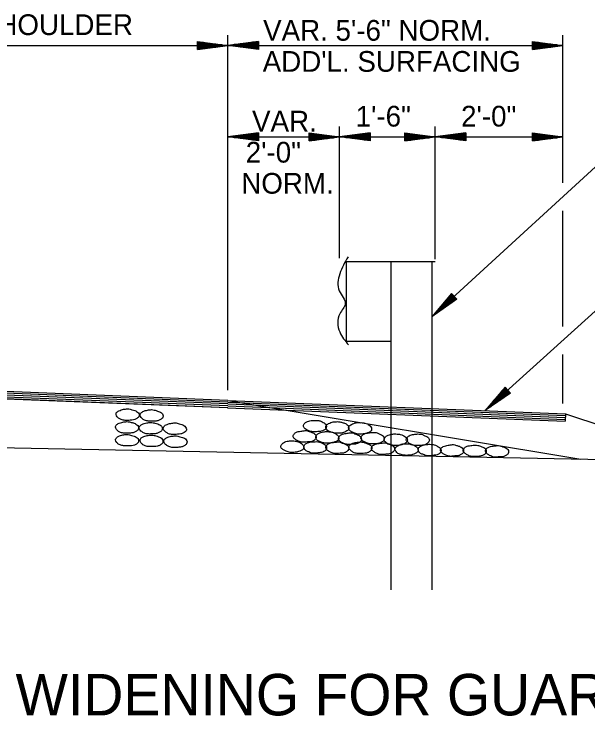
# Model space of a CAD drawing. Extents: x -2842 to 2681, y -2139 to 474.
# Drawn here: x 439.5 to 605.6, y -1543.1 to -1339.9 of the extents above; entities that cross this region are included whole.
import ezdxf

# ---------------------------------------------------------------- set-up
doc = ezdxf.new("R2010")
doc.units = 0
for name, color, linetype in [('BDR_Plan Profile Grid 3', 7, 'Continuous'), ('R_Border', 7, 'Continuous'), ('R_Border Notes', 7, 'Continuous'), ('SHT_NPLT', 7, 'Continuous')]:
    doc.layers.add(name, color=color, linetype=linetype)

msp = doc.modelspace()

# ---------------------------------------------------------------- linework, layer by layer
at = {"layer": 'BDR_Plan Profile Grid 3'}
for p, q in [((501.39, -1451.78), (394.39, -1447.45)), ((501.39, -1452.27), (394.39, -1448.03)), ((501.39, -1452.8), (394.39, -1448.57)), ((501.35, -1453.92), (394.35, -1449.59)), ((501.39, -1453.38), (394.39, -1449.1)), ((501.35, -1453.96), (394.39, -1449.68)), ((501.39, -1451.78), (603.52, -1468.78)), ((356.1, -1463.82), (640.63, -1469.52))]:
    msp.add_line(p, q, dxfattribs=at)
for points in [[(472.41, -1454.23), (471.21, -1454.36), (469.87, -1454.81), (469.11, -1455.39), (469.03, -1455.83), (469.34, -1456.55), (469.74, -1456.9), (470.54, -1457.31), (471.66, -1457.57), (472.28, -1457.57), (473.17, -1457.53), (474.11, -1457.44), (474.87, -1457.13), (475.62, -1456.5), (475.76, -1456.06), (475.53, -1455.39), (475, -1454.99), (474.46, -1454.72), (473.62, -1454.5), (473.13, -1454.32), (472.41, -1454.23)], [(479.32, -1454.45), (478.16, -1454.59), (476.78, -1455.03), (476.11, -1455.66), (476.02, -1456.06), (476.34, -1456.77), (476.69, -1457.13), (477.54, -1457.57), (478.66, -1457.8), (479.23, -1457.8), (480.13, -1457.8), (481.11, -1457.66), (481.87, -1457.35), (482.58, -1456.68), (482.67, -1456.28), (482.44, -1455.66), (481.91, -1455.21), (481.37, -1454.99), (480.62, -1454.72), (480.08, -1454.59), (479.32, -1454.45)], [(472.19, -1457.93), (471.03, -1458.06), (469.65, -1458.51), (468.94, -1459.13), (468.85, -1459.49), (469.16, -1460.2), (469.56, -1460.61), (470.32, -1461.05), (471.48, -1461.27), (472.1, -1461.27), (472.99, -1461.23), (473.97, -1461.14), (474.73, -1460.78), (475.45, -1460.16), (475.53, -1459.71), (475.36, -1459.04), (474.78, -1458.64), (474.29, -1458.38), (473.44, -1458.15), (472.95, -1458.02), (472.19, -1457.93)], [(479.06, -1458.15), (477.9, -1458.29), (476.52, -1458.73), (475.85, -1459.36), (475.71, -1459.71), (476.02, -1460.43), (476.47, -1460.83), (477.23, -1461.27), (478.39, -1461.5), (478.97, -1461.5), (479.86, -1461.45), (480.84, -1461.36), (481.6, -1461.01), (482.31, -1460.38), (482.44, -1459.94), (482.22, -1459.27), (481.69, -1458.87), (481.15, -1458.6), (480.3, -1458.38), (479.81, -1458.24), (479.06, -1458.15)], [(486.06, -1458.29), (484.85, -1458.42), (483.51, -1458.87), (482.8, -1459.49), (482.71, -1459.89), (483.02, -1460.61), (483.43, -1460.96), (484.18, -1461.41), (485.34, -1461.68), (485.97, -1461.68), (486.86, -1461.59), (487.79, -1461.5), (488.55, -1461.18), (489.31, -1460.56), (489.4, -1460.11), (489.18, -1459.49), (488.64, -1459.04), (488.11, -1458.78), (487.3, -1458.55), (486.77, -1458.38), (486.06, -1458.29)], [(526.67, -1457.57), (525.51, -1457.62), (524.09, -1458.06), (523.33, -1458.73), (523.24, -1459.13), (523.6, -1459.85), (524, -1460.16), (524.84, -1460.56), (526, -1460.87), (526.58, -1460.87), (527.43, -1460.83), (528.41, -1460.69), (529.12, -1460.43), (529.79, -1459.8), (529.88, -1459.36), (529.7, -1458.69), (529.21, -1458.29), (528.72, -1458.02), (527.92, -1457.66), (527.43, -1457.57), (526.67, -1457.57)], [(533.09, -1457.93), (531.89, -1458.02), (530.51, -1458.51), (529.79, -1459.09), (529.7, -1459.49), (530.06, -1460.25), (530.42, -1460.61), (531.26, -1460.96), (532.33, -1461.23), (532.91, -1461.27), (533.8, -1461.27), (534.83, -1461.1), (535.54, -1460.74), (536.3, -1460.2), (536.39, -1459.71), (536.17, -1459.09), (535.63, -1458.6), (535.14, -1458.38), (534.29, -1458.11), (533.8, -1458.02), (533.09, -1457.93)], [(539.73, -1458.24), (538.53, -1458.24), (537.15, -1458.73), (536.39, -1459.4), (536.3, -1459.8), (536.7, -1460.52), (537.1, -1460.83), (537.86, -1461.18), (539.02, -1461.54), (539.6, -1461.59), (540.49, -1461.5), (541.43, -1461.32), (542.19, -1461.05), (542.9, -1460.47), (542.99, -1460.03), (542.77, -1459.4), (542.28, -1458.96), (541.74, -1458.6), (540.98, -1458.38), (540.49, -1458.24), (539.73, -1458.24)], [(523.73, -1460.52), (522.48, -1460.69), (521.1, -1461.05), (520.39, -1461.72), (520.25, -1462.12), (520.65, -1462.83), (521.05, -1463.19), (521.81, -1463.59), (522.97, -1463.9), (523.55, -1463.9), (524.44, -1463.82), (525.47, -1463.73), (526.23, -1463.41), (526.85, -1462.79), (526.94, -1462.3), (526.72, -1461.68), (526.23, -1461.27), (525.69, -1461.05), (524.89, -1460.74), (524.44, -1460.56), (523.73, -1460.52)], [(530.24, -1460.83), (529.03, -1460.87), (527.61, -1461.36), (526.89, -1462.03), (526.81, -1462.39), (527.16, -1463.15), (527.56, -1463.5), (528.37, -1463.86), (529.48, -1464.13), (530.1, -1464.17), (530.95, -1464.13), (531.93, -1463.95), (532.69, -1463.64), (533.36, -1463.1), (533.49, -1462.61), (533.27, -1461.99), (532.73, -1461.59), (532.24, -1461.23), (531.44, -1460.96), (530.95, -1460.87), (530.24, -1460.83)], [(543.3, -1461.05), (542.1, -1461.18), (540.71, -1461.54), (540, -1462.21), (539.87, -1462.61), (540.27, -1463.37), (540.71, -1463.68), (541.47, -1464.08), (542.63, -1464.39), (543.17, -1464.39), (544.06, -1464.31), (545.04, -1464.26), (545.84, -1463.9), (546.51, -1463.28), (546.6, -1462.83), (546.38, -1462.17), (545.84, -1461.76), (545.31, -1461.54), (544.55, -1461.18), (544.06, -1461.05), (543.3, -1461.05)], [(472.19, -1461.63), (471.03, -1461.76), (469.69, -1462.21), (469.03, -1462.79), (468.89, -1463.24), (469.25, -1463.95), (469.6, -1464.31), (470.41, -1464.71), (471.52, -1464.97), (472.15, -1464.97), (473.04, -1464.93), (473.97, -1464.84), (474.73, -1464.53), (475.49, -1463.9), (475.58, -1463.46), (475.36, -1462.79), (474.82, -1462.39), (474.29, -1462.12), (473.48, -1461.9), (472.95, -1461.72), (472.19, -1461.63)], [(479.28, -1461.81), (478.08, -1461.94), (476.74, -1462.39), (476.07, -1462.97), (475.98, -1463.41), (476.29, -1464.13), (476.65, -1464.48), (477.45, -1464.93), (478.57, -1465.15), (479.19, -1465.15), (480.08, -1465.11), (481.02, -1465.02), (481.82, -1464.71), (482.53, -1464.04), (482.62, -1463.64), (482.4, -1462.97), (481.87, -1462.52), (481.33, -1462.3), (480.57, -1462.03), (480.04, -1461.9), (479.28, -1461.81)], [(486.19, -1462.03), (485.03, -1462.17), (483.65, -1462.61), (482.98, -1463.24), (482.89, -1463.64), (483.2, -1464.31), (483.6, -1464.71), (484.36, -1465.15), (485.52, -1465.42), (486.06, -1465.42), (486.95, -1465.38), (487.93, -1465.24), (488.73, -1464.93), (489.44, -1464.31), (489.58, -1463.82), (489.36, -1463.19), (488.82, -1462.75), (488.24, -1462.52), (487.48, -1462.3), (486.95, -1462.12), (486.19, -1462.03)], [(536.79, -1461.18), (535.63, -1461.32), (534.21, -1461.72), (533.45, -1462.39), (533.36, -1462.79), (533.72, -1463.5), (534.12, -1463.82), (534.92, -1464.26), (536.03, -1464.53), (536.66, -1464.53), (537.5, -1464.48), (538.53, -1464.39), (539.24, -1464.08), (539.96, -1463.46), (540.05, -1462.97), (539.82, -1462.34), (539.33, -1461.94), (538.8, -1461.68), (538.04, -1461.41), (537.55, -1461.18), (536.79, -1461.18)], [(550.03, -1461.5), (548.87, -1461.54), (547.4, -1462.03), (546.73, -1462.7), (546.6, -1463.06), (547, -1463.82), (547.4, -1464.13), (548.16, -1464.48), (549.32, -1464.8), (549.9, -1464.84), (550.79, -1464.8), (551.73, -1464.62), (552.48, -1464.31), (553.2, -1463.73), (553.33, -1463.28), (553.11, -1462.66), (552.57, -1462.21), (552.08, -1461.9), (551.28, -1461.63), (550.79, -1461.54), (550.03, -1461.5)], [(556.36, -1461.5), (555.2, -1461.63), (553.82, -1462.03), (553.11, -1462.7), (552.98, -1463.06), (553.42, -1463.82), (553.78, -1464.13), (554.58, -1464.57), (555.69, -1464.84), (556.27, -1464.84), (557.17, -1464.8), (558.15, -1464.71), (558.9, -1464.35), (559.57, -1463.73), (559.71, -1463.28), (559.48, -1462.66), (558.95, -1462.21), (558.41, -1462.03), (557.66, -1461.63), (557.12, -1461.54), (556.36, -1461.5)], [(520.12, -1463.5), (518.91, -1463.55), (517.49, -1464.04), (516.82, -1464.71), (516.68, -1465.11), (517.09, -1465.82), (517.49, -1466.13), (518.25, -1466.49), (519.4, -1466.85), (519.98, -1466.85), (520.88, -1466.8), (521.81, -1466.62), (522.57, -1466.31), (523.28, -1465.73), (523.37, -1465.33), (523.15, -1464.71), (522.66, -1464.26), (522.12, -1463.9), (521.32, -1463.64), (520.88, -1463.55), (520.12, -1463.5)], [(526.67, -1463.73), (525.51, -1463.82), (524.09, -1464.26), (523.42, -1464.89), (523.33, -1465.33), (523.68, -1466.04), (524, -1466.36), (524.84, -1466.71), (525.96, -1467.07), (526.54, -1467.07), (527.43, -1466.98), (528.45, -1466.85), (529.17, -1466.62), (529.84, -1465.96), (529.97, -1465.51), (529.79, -1464.89), (529.21, -1464.48), (528.68, -1464.13), (527.92, -1463.86), (527.43, -1463.73), (526.67, -1463.73)], [(533.14, -1463.82), (531.93, -1463.95), (530.51, -1464.35), (529.79, -1464.97), (529.7, -1465.42), (530.06, -1466.13), (530.46, -1466.45), (531.26, -1466.89), (532.38, -1467.16), (532.96, -1467.16), (533.85, -1467.07), (534.83, -1467.03), (535.59, -1466.71), (536.26, -1466.04), (536.39, -1465.64), (536.17, -1464.97), (535.63, -1464.57), (535.1, -1464.31), (534.29, -1464.04), (533.85, -1463.86), (533.14, -1463.82)], [(539.82, -1463.82), (538.62, -1463.95), (537.19, -1464.35), (536.48, -1464.97), (536.35, -1465.42), (536.75, -1466.13), (537.15, -1466.45), (537.95, -1466.94), (539.07, -1467.16), (539.64, -1467.16), (540.54, -1467.11), (541.52, -1467.03), (542.28, -1466.71), (542.94, -1466.04), (543.08, -1465.64), (542.85, -1464.97), (542.32, -1464.53), (541.78, -1464.31), (541.03, -1464.04), (540.54, -1463.9), (539.82, -1463.82)], [(546.38, -1464.08), (545.17, -1464.22), (543.79, -1464.57), (543.03, -1465.24), (542.94, -1465.64), (543.3, -1466.4), (543.7, -1466.71), (544.55, -1467.16), (545.62, -1467.43), (546.2, -1467.43), (547.09, -1467.38), (548.12, -1467.29), (548.87, -1466.94), (549.54, -1466.31), (549.63, -1465.87), (549.41, -1465.2), (548.87, -1464.8), (548.38, -1464.57), (547.63, -1464.31), (547.13, -1464.08), (546.38, -1464.08)], [(553.11, -1464.35), (551.91, -1464.39), (550.52, -1464.93), (549.85, -1465.51), (549.72, -1465.87), (550.12, -1466.62), (550.43, -1467.03), (551.28, -1467.38), (552.35, -1467.65), (552.98, -1467.69), (553.87, -1467.65), (554.85, -1467.47), (555.56, -1467.16), (556.32, -1466.58), (556.45, -1466.13), (556.23, -1465.51), (555.69, -1465.02), (555.16, -1464.75), (554.36, -1464.53), (553.87, -1464.39), (553.11, -1464.35)], [(559.8, -1464.48), (558.64, -1464.57), (557.21, -1465.02), (556.54, -1465.64), (556.45, -1466.09), (556.76, -1466.8), (557.12, -1467.11), (557.97, -1467.47), (559.04, -1467.83), (559.66, -1467.83), (560.55, -1467.74), (561.58, -1467.6), (562.29, -1467.38), (563.01, -1466.71), (563.1, -1466.31), (562.87, -1465.64), (562.34, -1465.24), (561.8, -1464.93), (561.04, -1464.62), (560.55, -1464.53), (559.8, -1464.48)], [(566.35, -1464.57), (565.15, -1464.75), (563.72, -1465.15), (563.01, -1465.78), (562.92, -1466.18), (563.27, -1466.94), (563.68, -1467.2), (564.48, -1467.65), (565.59, -1467.96), (566.17, -1467.96), (567.06, -1467.87), (568.04, -1467.83), (568.8, -1467.47), (569.52, -1466.85), (569.6, -1466.4), (569.38, -1465.78), (568.85, -1465.33), (568.36, -1465.06), (567.51, -1464.8), (567.06, -1464.62), (566.35, -1464.57)], [(572.95, -1464.71), (571.7, -1464.84), (570.27, -1465.2), (569.6, -1465.87), (569.47, -1466.27), (569.87, -1466.98), (570.27, -1467.29), (571.08, -1467.78), (572.19, -1468.05), (572.77, -1468.05), (573.66, -1468.01), (574.64, -1467.87), (575.4, -1467.56), (576.07, -1466.94), (576.16, -1466.49), (575.98, -1465.87), (575.45, -1465.42), (574.87, -1465.2), (574.15, -1464.93), (573.71, -1464.8), (572.95, -1464.71)], [(579.37, -1464.84), (578.12, -1465.02), (576.74, -1465.38), (576.02, -1466.04), (575.94, -1466.45), (576.29, -1467.16), (576.69, -1467.47), (577.5, -1467.87), (578.61, -1468.23), (579.19, -1468.23), (580.08, -1468.1), (581.06, -1468.1), (581.82, -1467.74), (582.53, -1467.11), (582.62, -1466.62), (582.4, -1466), (581.87, -1465.6), (581.33, -1465.33), (580.62, -1465.06), (580.08, -1464.93), (579.37, -1464.84)]]:
    msp.add_spline(points, degree=3, dxfattribs=at)
at = {"layer": 'R_Border Notes'}
for p, q in [((501.39, -1448.78), (501.39, -1346.01)), ((598.32, -1388.76), (598.32, -1346.01)), ((358.73, -1349.01), (501.39, -1349.01)), ((492.56, -1348.33), (496.09, -1348.32)), ((492.56, -1348.56), (497.87, -1348.56)), ((492.57, -1347.87), (501.39, -1349.01)), ((492.57, -1350.16), (492.57, -1347.87)), ((492.57, -1348.1), (494.3, -1348.09)), ((492.57, -1348.79), (499.6, -1348.79)), ((501.39, -1349.01), (492.57, -1349.01)), ((492.57, -1350.16), (501.39, -1349.01)), ((492.57, -1349.24), (499.6, -1349.24)), ((510.21, -1347.86), (501.39, -1349.01)), ((501.39, -1349.01), (598.32, -1349.01)), ((501.39, -1349.01), (510.22, -1349.01)), ((510.22, -1350.15), (501.39, -1349.01)), ((510.21, -1348.78), (503.18, -1348.79)), ((510.22, -1349.23), (503.18, -1349.24)), ((510.22, -1348.56), (504.91, -1348.56)), ((510.21, -1348.32), (506.69, -1348.32)), ((510.22, -1348.09), (508.48, -1348.1)), ((510.21, -1347.86), (510.22, -1350.15)), ((589.49, -1347.87), (598.32, -1349.01)), ((589.5, -1350.16), (589.49, -1347.87)), ((589.49, -1348.1), (591.22, -1348.09)), ((589.49, -1348.33), (593.01, -1348.32)), ((589.49, -1348.56), (594.79, -1348.56)), ((589.49, -1348.79), (596.52, -1348.79)), ((598.32, -1349.01), (589.49, -1349.01)), ((589.5, -1350.16), (598.32, -1349.01)), ((589.5, -1349.24), (596.53, -1349.24)), ((492.57, -1349.47), (497.87, -1349.47)), ((492.57, -1349.7), (496.09, -1349.7)), ((492.57, -1349.93), (494.3, -1349.93)), ((510.22, -1349.47), (504.92, -1349.47)), ((510.22, -1349.7), (506.7, -1349.7)), ((510.22, -1349.93), (508.49, -1349.93)), ((589.49, -1349.47), (594.8, -1349.47)), ((589.49, -1349.93), (591.23, -1349.93)), ((589.5, -1349.7), (593.02, -1349.7)), ((533.72, -1410.62), (533.72, -1372.5)), ((561.4, -1410.89), (561.4, -1372.5)), ((510.21, -1374.35), (501.39, -1375.5)), ((501.39, -1375.5), (533.72, -1375.5)), ((501.39, -1375.5), (510.22, -1375.5)), ((510.22, -1376.64), (501.39, -1375.5)), ((510.21, -1375.27), (503.18, -1375.27)), ((510.22, -1375.72), (503.18, -1375.72)), ((510.22, -1375.04), (504.91, -1375.04)), ((510.21, -1374.8), (506.69, -1374.81)), ((510.22, -1374.58), (508.48, -1374.58)), ((510.21, -1374.35), (510.22, -1376.64)), ((524.89, -1374.36), (533.72, -1375.5)), ((524.89, -1376.64), (524.89, -1374.36)), ((524.89, -1374.58), (526.62, -1374.58)), ((524.89, -1374.81), (528.41, -1374.81)), ((524.89, -1375.04), (530.19, -1375.04)), ((524.89, -1375.28), (531.92, -1375.27)), ((533.72, -1375.5), (524.89, -1375.5)), ((524.89, -1376.64), (533.72, -1375.5)), ((524.9, -1375.72), (531.93, -1375.72)), ((542.54, -1374.35), (533.72, -1375.5)), ((533.72, -1375.5), (561.4, -1375.5)), ((533.72, -1375.5), (542.54, -1375.5)), ((542.54, -1376.64), (533.72, -1375.5)), ((542.54, -1375.27), (535.51, -1375.27)), ((542.54, -1375.72), (535.51, -1375.72)), ((542.54, -1375.04), (537.24, -1375.04)), ((542.53, -1374.8), (539.02, -1374.81)), ((542.54, -1374.58), (540.8, -1374.58)), ((542.54, -1374.35), (542.54, -1376.64)), ((552.57, -1374.81), (556.1, -1374.81)), ((552.57, -1375.04), (557.88, -1375.04)), ((552.58, -1374.36), (561.4, -1375.5)), ((552.58, -1376.64), (552.58, -1374.36)), ((552.58, -1374.58), (554.31, -1374.58)), ((552.58, -1375.28), (559.61, -1375.27)), ((561.4, -1375.5), (552.58, -1375.5)), ((552.58, -1376.64), (561.4, -1375.5)), ((552.58, -1375.72), (559.61, -1375.72)), ((570.22, -1374.35), (561.4, -1375.5)), ((561.4, -1375.5), (598.32, -1375.5)), ((561.4, -1375.5), (570.22, -1375.5)), ((570.23, -1376.64), (561.4, -1375.5)), ((570.22, -1375.27), (563.19, -1375.27)), ((570.23, -1375.72), (563.19, -1375.72)), ((570.23, -1375.04), (564.92, -1375.04)), ((570.22, -1374.8), (566.7, -1374.81)), ((570.23, -1374.58), (568.49, -1374.58)), ((570.22, -1374.35), (570.23, -1376.64)), ((589.49, -1374.36), (598.32, -1375.5)), ((589.5, -1376.64), (589.49, -1374.36)), ((589.49, -1374.58), (591.22, -1374.58)), ((589.49, -1374.81), (593.01, -1374.81)), ((589.49, -1375.04), (594.79, -1375.04)), ((589.49, -1375.28), (596.52, -1375.27)), ((598.32, -1375.5), (589.49, -1375.5)), ((589.5, -1376.64), (598.32, -1375.5)), ((589.5, -1375.72), (596.53, -1375.72)), ((510.22, -1375.95), (504.92, -1375.95)), ((510.22, -1376.18), (506.7, -1376.19)), ((510.22, -1376.41), (508.49, -1376.42)), ((524.89, -1375.95), (530.2, -1375.95)), ((524.89, -1376.42), (526.63, -1376.41)), ((524.9, -1376.19), (528.41, -1376.18)), ((542.54, -1375.95), (537.24, -1375.95)), ((542.54, -1376.18), (539.02, -1376.19)), ((542.54, -1376.41), (540.81, -1376.42)), ((552.58, -1375.95), (557.88, -1375.95)), ((552.58, -1376.19), (556.1, -1376.18)), ((552.58, -1376.42), (554.31, -1376.41)), ((570.23, -1375.95), (564.92, -1375.95)), ((570.23, -1376.18), (566.71, -1376.19)), ((570.23, -1376.41), (568.5, -1376.42)), ((589.49, -1375.95), (594.8, -1375.95)), ((589.49, -1376.42), (591.23, -1376.41)), ((589.5, -1376.19), (593.02, -1376.18)), ((598.32, -1430.38), (598.32, -1396.9)), ((566.1, -1420.8), (560.38, -1427.61)), ((560.38, -1427.61), (566.88, -1421.65)), ((566.72, -1421.48), (561.54, -1426.23)), ((567.03, -1421.81), (561.85, -1426.57)), ((566.57, -1421.31), (562.67, -1424.9)), ((567.19, -1421.98), (563.28, -1425.57)), ((566.41, -1421.14), (563.82, -1423.52)), ((567.34, -1422.15), (564.75, -1424.53)), ((566.26, -1420.97), (564.98, -1422.15)), ((566.1, -1420.8), (567.65, -1422.49)), ((567.5, -1422.32), (566.23, -1423.49)), ((567.65, -1422.49), (560.38, -1427.61)), ((598.32, -1452.63), (598.32, -1438.47)), ((581.63, -1447.97), (575.86, -1454.74)), ((575.86, -1454.74), (582.4, -1448.82)), ((582.25, -1448.65), (577.03, -1453.37)), ((582.1, -1448.48), (578.17, -1452.04)), ((581.94, -1448.31), (579.33, -1450.67)), ((581.79, -1448.13), (580.5, -1449.31)), ((581.63, -1447.97), (583.17, -1449.66)), ((583.17, -1449.66), (575.86, -1454.74)), ((582.55, -1448.98), (577.34, -1453.7)), ((582.71, -1449.15), (578.78, -1452.71)), ((582.86, -1449.32), (580.26, -1451.69)), ((583.02, -1449.49), (581.74, -1450.66))]:
    msp.add_line(p, q, dxfattribs=at)
for points in [[(627.78, -1373.58), (619.32, -1373.58), (560.38, -1427.61)], [(635.72, -1408.01), (627.52, -1408.01), (575.86, -1454.74)]]:
    msp.add_lwpolyline(points, dxfattribs=at)
at = {"layer": 'SHT_NPLT'}
for p, q in [((535.59, -1411.52), (535.59, -1434.61)), ((535.59, -1411.52), (561.4, -1411.52)), ((548.52, -1411.52), (548.52, -1506.62)), ((560.38, -1411.61), (560.38, -1506.66)), ((535.59, -1434.61), (548.52, -1434.61)), ((501.39, -1451.78), (599.03, -1455.66)), ((501.39, -1452.27), (598.99, -1456.19)), ((501.39, -1452.8), (598.94, -1456.73)), ((501.3, -1453.92), (598.94, -1457.8)), ((501.35, -1453.38), (598.94, -1457.26)), ((599.03, -1455.66), (598.94, -1457.8)), ((599.03, -1455.66), (717.26, -1494.98))]:
    msp.add_line(p, q, dxfattribs=at)
msp.add_spline([(536.17, -1410.18), (533.76, -1415.17), (533.63, -1420.08), (535.36, -1423.82), (533.76, -1426.68), (533.76, -1431.94), (536.3, -1435.73)], degree=3, dxfattribs=at)

# ---------------------------------------------------------------- texts
at = {"layer": 'R_Border'}
for s, height, p in [('8\' - 0" NORMAL SHOULDER', 6, (370.13, -1346.01)), ('VAR. 5\'-6" NORM.', 6, (511.59, -1347.64)), ("ADD'L. SURFACING", 6, (511.47, -1356.64)), ('1\'-6"', 6, (538.37, -1372.5)), ('2\'-0"', 6, (568.87, -1372.5)), ('VAR.', 6, (508.39, -1373.93)), ('2\'-0"', 6, (506.57, -1382.93)), ('NORM.', 6, (505.27, -1391.93)), (' WIDENING FOR GUARDRAIL ', 12, (435.51, -1542.97))]:
    msp.add_text(s, height=height, dxfattribs=at).set_placement(p)

doc.saveas('drawing.dxf')
